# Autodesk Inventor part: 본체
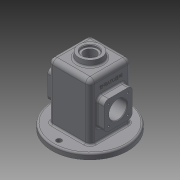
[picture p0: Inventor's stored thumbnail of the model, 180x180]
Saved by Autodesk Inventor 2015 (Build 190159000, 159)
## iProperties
Created: 2021-08
Part Number: 본체
Material: 일반
Document SubType Name: Modeling
Designer: 104-00
Density: 1 g/cm^3
Appearance: 기본값
Mass: 304.336 g
Surface Area: 949.017 cm^2
Volume: 304.336 cm^3
Author: 104-00
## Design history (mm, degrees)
sketch "스케치1"
  geometry: C1 r 67 at (0, 0); 1 further point
  constraints: 1 centre point, 1 coincident
  dimensions: "d0" = 134 diameter of C1
extrude "돌출1" new body sketch "스케치1" distance "d1" = 10; taper "d2" = 0 deg
sketch "스케치2"
  geometry: L1 (-37, -37)-(37, -37); L2 (37, -37)-(37, 37); L3 (37, 37)-(-37, 37); L4 (-37, 37)-(-37, -37); L5 (-37, -37)-(37, 37); L6 (37, -37)-(-37, 37); C1 r 67 at (0, 0) reference; 2 further points
  constraints: 12 end point, 3 midpoint, 2 parallel, 1 coincident, 1 horizontal, 1 perpendicular
  dimensions: "d3" = 74 distance of L2.end L3.end; "d4" = 74 distance of L3.end L1.start
extrude "돌출2" join sketch "스케치2" distance "d5" = 100; taper "d6" = 0 deg
fillet "모깎기5" dims "d19" = 8
fillet "모깎기6" dims "d20" = 8
sketch "스케치5"
  geometry: L1 (32, 32)-(-32, 32); L2 (-32, 32)-(-32, -32); L3 (-32, -32)-(32, -32); L4 (32, -32)-(32, 32); L5 (32, 32)-(-32, -32); L6 (-32, 32)-(32, -32); C1 r 67 at (0, 0) reference; 1 further point
  constraints: 12 end point, 2 midpoint, 2 parallel, 1 horizontal, 1 perpendicular
  dimensions: "d21" = 64 distance of L2.end L3.end; "d22" = 64 distance of L3.end L1.start
extrude "돌출4" cut sketch "스케치5" distance "d23" = 105; taper "d24" = 0 deg
fillet "모깎기7" dims "d25" = 3
fillet "모깎기8" dims "d26" = 3
sketch "스케치6"
  geometry: L1 (20, 54)-(70, 54); L2 (70, 54)-(70, 4); L3 (70, 4)-(20, 4); L4 (20, 4)-(20, 54); L5 (20, 54)-(70, 4); L6 (70, 54)-(20, 4); L7 (-10, 96)-(-10, -38) reference; L8 (92, 66)-(0, 66) reference; 2 further points
  constraints: 12 end point, 2 midpoint, 2 parallel, 1 horizontal, 1 perpendicular
  dimensions: "d27" = 55 distance from line of L7 point (45, 29); "d28" = 37 distance from line of L8 point (45, 29); "d29" = 50 distance of L1.end L2.end; "d30" = 50 distance of L2.end L3.end
extrude "돌출5" join sketch "스케치6" distance "d31" = 13; taper "d32" = 0 deg
sketch "스케치7"
  geometry: L1 (-102, 66)-(-10, 66) reference; L2 (-80, 54)-(-30, 54) reference; L3 (-30, 54)-(-30, 4) reference; L4 (-30, 4)-(-80, 4) reference; L5 (-80, 4)-(-80, 54) reference; L6 (-10, 87.864)-(0, 87.864) reference; L7 (0, 87.864)-(0, 58) reference; L8 (-102, 58)-(0, 58) reference; L9 (-102, 0)-(-102, 58) reference; L10 (-102, 0)-(0, 0) reference; L11 (0, 0)-(0, -29.864) reference; L12 (0, -29.864)-(-10, -29.864) reference; L13 (-10, -29.864)-(-10, -7.416) reference; L14 (-10, -7.416)-(-102, -7.416) reference; L15 (-109.416, 0)-(-109.416, 58) reference; L16 (-102, 65.416)-(-10, 65.416) reference; L17 (-10, 65.416)-(-10, 87.864) reference; L18 (0, 58)-(0, 0) reference; C1 r 25 at (-55, 29); A1 r 7.416 centre (-102, 0) between (-109.416, 0) and (-102, -7.416) reference; A2 r 7.416 centre (-102, 58) between (-102, 65.416) and (-109.416, 58) reference; 1 further point
  constraints: 1 centre point
  dimensions: "d33" = 50 diameter of C1; "d34" = 55 distance from line of L7 C1.centre; "d89" = 37 distance from line of C1.centre L1
extrude "돌출6" join sketch "스케치7" distance "d36" = 7; taper "d37" = -20 deg
sketch "스케치8"
  geometry: C1 r 25 at (45, 29) reference; 2 further points
  constraints: 1 coincident
hole "구멍1" sketch "스케치8" at (45, 29) diameter "d38" = 32; stored, may be unused: countersink angle "d42" = 90 deg, drill point angle "d44" = 118 deg; dims "d39" = 6, "d40" = 4, "d41" = 2, "d43" = 8
sketch "스케치9"
  geometry: C1 r 67 at (0, 0) reference; 3 further points
  constraints: 2 vertical alignment
  dimensions: "d45" = 55 distance of C1.centre point (0, 55); "d46" = 55 distance of C1.centre point (0, -55)
hole "구멍2" sketch "스케치9" at (0, 55), (0, -55) diameter "d47" = 9; stored, may be unused: countersink angle "d51" = 90 deg, drill point angle "d53" = 118 deg; dims "d48" = 6, "d49" = 4, "d50" = 2, "d52" = 8
sketch "스케치10" dims "d23" = 105
  geometry: C1 r 16 at (25, 25) reference; 2 further points
  dimensions: "d54" = 17 horizontal distance of point (8, 42) C1.centre; "d55" = 17 horizontal distance of C1.centre point (8, 42)
hole "구멍3" sketch "스케치10" at (8, 42) diameter "d56" = 3.242; stored, may be unused: countersink angle "d60" = 90 deg, drill point angle "d62" = 118 deg; dims "d23" = 105, "d57" = 8, "d58" = 4, "d59" = 2, "d61" = 10
sketch "스케치11"
  geometry: C1 r 20 at (0, 0); 1 further point
  constraints: 1 centre point, 1 coincident
  dimensions: "d69" = 40 diameter of C1
extrude "돌출7" join sketch "스케치11" distance "d70" = 10; taper "d71" = 0 deg
feature "면 기울기1" dims angle "d90" = 6 deg
sketch "스케치12"
  geometry: C1 r 20 at (0, 0) reference
hole "구멍4" sketch "스케치12" at (0, 0) diameter "d72" = 21; stored, may be unused: countersink angle "d76" = 90 deg, drill point angle "d78" = 118 deg; dims "d73" = 8, "d74" = 28, "d75" = 4, "d77" = 20
sketch "스케치13"
  geometry: L1 (-110, 49)-(-110, 9) reference; L2 (-92, -8)-(0, -8) reference; 2 further points
  constraints: 1 other
  dimensions: "d80" = 37 distance from line of L2 point (-82, 29); "d91" = 28 distance from line of point (-82, 29) L1
feature "엠보싱2" sketch "스케치13" dims "d92" = 0.5, "d93" = 0
fillet "모깎기9" dims "d83" = 8
fillet "모깎기10" dims "d84" = 8
fillet "모깎기11" dims "d85" = 3
chamfer "모따기1" distance "d86" = 1; stored, may be unused: second distance "d87" = 2, angle "d88" = 45 deg
node "솔리드1"
mirror "대칭1"
pattern_linear "직사각형 패턴1" dims "d65" = 34, "d68" = 34
mirror "대칭2"
node "투영된 루프1"
node "절단 모서리 투영1"
